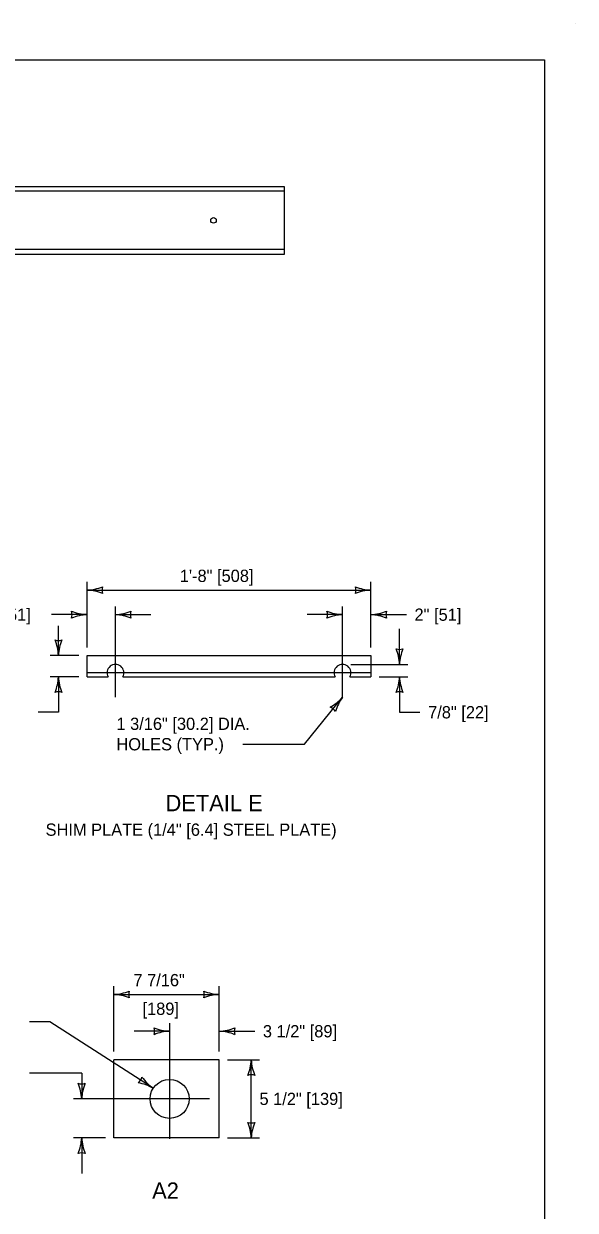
# Model space of a CAD drawing. Extents: x 49991.4 to 50021, y 49987.6 to 50011.4.
# Drawn here: x 50014.2 to 50016.9, y 49993.37 to 49999.18 of the extents above; entities that cross this region are included whole.
import ezdxf

# ---------------------------------------------------------------- set-up
doc = ezdxf.new("R2010")
doc.units = 0
for name, color, linetype in [('Level 1', 7, 'Continuous'), ('Level 2', 7, 'Continuous'), ('Level 3', 7, 'Continuous'), ('Level 4', 7, 'Continuous'), ('Level 5', 7, 'Continuous')]:
    doc.layers.add(name, color=color, linetype=linetype)

msp = doc.modelspace()

# ---------------------------------------------------------------- linework, layer by layer
at = {"layer": 'Level 1'}
for p, q in [((50016.9001, 49999.1756), (50016.9001, 49999.1756)), ((50015.4779, 49998.377), (50009.801, 49998.377)), ((50015.4779, 49998.0488), (50015.4779, 49998.377)), ((50009.7464, 49998.0488), (50015.4779, 49998.0488)), ((50014.5111, 49996.0841), (50015.9001, 49996.0841)), ((50014.5111, 49995.98), (50014.5111, 49996.0841)), ((50015.9001, 49996.0841), (50015.9001, 49995.98)), ((50014.5111, 49995.98), (50014.6137, 49995.98)), ((50014.6863, 49995.98), (50015.7249, 49995.98)), ((50015.7975, 49995.98), (50015.9001, 49995.98)), ((50015.158, 49994.1057), (50014.6415, 49994.1057)), ((50014.6415, 49993.7237), (50014.6415, 49994.1057)), ((50015.158, 49993.7237), (50015.158, 49994.1057)), ((50015.158, 49993.7237), (50014.6415, 49993.7237))]:
    msp.add_line(p, q, dxfattribs=at)
msp.add_lwpolyline([(49999.3835, 49998.9992), (50016.7501, 49998.9992), (50016.7501, 49987.7988), (49999.3835, 49987.7988)], close=True, dxfattribs=at)
for centre, radius in [((50015.1299, 49998.2132), 0.0136), ((50014.9149, 49993.9147), 0.0955)]:
    msp.add_circle(centre, radius, dxfattribs=at)
for centre in [(50014.65, 49995.9995), (50015.7612, 49995.9995)]:
    msp.add_arc(centre, 0.0412, 331.72619, 208.27381, dxfattribs=at)
at = {"layer": 'Level 3'}
for p, q in [((50014.5111, 49996.1241), (50014.5111, 49996.4441)), ((50015.9001, 49996.1241), (50015.9001, 49996.4441)), ((50014.5111, 49996.4041), (50015.9001, 49996.4041)), ((50014.5111, 49996.2841), (50014.3377, 49996.2841)), ((50014.65, 49996.2841), (50014.8235, 49996.2841)), ((50015.7612, 49996.2841), (50015.5877, 49996.2841)), ((50015.9001, 49996.2841), (50016.0735, 49996.2841)), ((50014.3711, 49996.0841), (50014.3711, 49996.2293)), ((50016.0401, 49996.0407), (50016.0401, 49996.2142)), ((50014.4711, 49996.0841), (50014.3311, 49996.0841)), ((50015.8012, 49996.0407), (50016.0801, 49996.0407)), ((50014.4711, 49995.98), (50014.3311, 49995.98)), ((50014.3711, 49995.98), (50014.3711, 49995.8065)), ((50015.9401, 49995.98), (50016.0801, 49995.98)), ((50016.0401, 49995.98), (50016.0401, 49995.8065)), ((50014.3711, 49995.8065), (50014.2711, 49995.8065)), ((50016.0401, 49995.8065), (50016.1401, 49995.8065)), ((50014.6415, 49994.1457), (50014.6415, 49994.4657)), ((50015.158, 49994.1457), (50015.158, 49994.4657)), ((50014.6415, 49994.4257), (50015.158, 49994.4257)), ((50014.3297, 49994.2911), (50014.2297, 49994.2911)), ((50014.8346, 49993.9664), (50014.3297, 49994.2911)), ((50014.9149, 49994.2457), (50014.7415, 49994.2457)), ((50015.158, 49994.2457), (50015.3314, 49994.2457)), ((50015.198, 49994.1057), (50015.3548, 49994.1057)), ((50015.3148, 49993.7237), (50015.3148, 49994.1057)), ((50014.4847, 49994.0399), (50014.2297, 49994.0399)), ((50014.4847, 49994.0399), (50014.4847, 49993.9147)), ((50014.6015, 49993.7237), (50014.4447, 49993.7237)), ((50014.4847, 49993.7237), (50014.4847, 49993.5503)), ((50015.198, 49993.7237), (50015.3548, 49993.7237))]:
    msp.add_line(p, q, dxfattribs=at)
msp.add_lwpolyline([(50015.2737, 49995.65), (50015.5749, 49995.65), (50015.7612, 49995.88)], dxfattribs=at)
for centre, radius, start, end in [((50014.4996, 49996.6368), 0.233, 272.82731, 292.07716), ((50014.6394, 49996.4041), 0.0548, 162.13882, 197.86118), ((50015.9092, 49996.6263), 0.2223, 247.45601, 267.63952), ((50015.7718, 49996.4041), 0.0548, 342.13882, 17.86118), ((50014.502, 49996.182), 0.2223, 67.45601, 87.63952), ((50015.9116, 49996.1714), 0.233, 92.82731, 112.07716), ((50014.5203, 49996.5063), 0.2223, 247.45601, 267.63952), ((50014.3829, 49996.2841), 0.0548, 342.13882, 17.86118), ((50014.6409, 49996.5063), 0.2223, 272.36048, 292.54399), ((50014.7782, 49996.2841), 0.0548, 162.13882, 197.86118), ((50015.7703, 49996.5063), 0.2223, 247.45601, 267.63952), ((50015.633, 49996.2841), 0.0548, 342.13882, 17.86118), ((50015.8909, 49996.5063), 0.2223, 272.36048, 292.54399), ((50016.0283, 49996.2841), 0.0548, 162.13882, 197.86118), ((50014.5226, 49996.0514), 0.233, 92.82731, 112.07716), ((50014.6385, 49996.0514), 0.233, 67.92284, 87.17269), ((50015.7727, 49996.0514), 0.233, 92.82731, 112.07716), ((50015.8886, 49996.0514), 0.233, 67.92284, 87.17269), ((50014.3711, 49996.2123), 0.0548, 252.13882, 287.86118), ((50014.1384, 49996.0726), 0.233, 2.82731, 22.07716), ((50014.5933, 49996.075), 0.2223, 157.45601, 177.63952), ((50015.8179, 49996.0316), 0.2223, 2.36048, 22.54399), ((50016.0401, 49996.1689), 0.0548, 252.13882, 287.86118), ((50016.2728, 49996.0292), 0.233, 157.92284, 177.17269), ((50014.1384, 49995.9915), 0.233, 337.92284, 357.17269), ((50014.5933, 49995.9891), 0.2223, 182.36048, 202.54399), ((50015.8179, 49995.9891), 0.2223, 337.45601, 357.63952), ((50016.2728, 49995.9915), 0.233, 182.82731, 202.07716), ((50014.3711, 49995.8517), 0.0548, 72.13882, 107.86118), ((50016.0401, 49995.8517), 0.0548, 72.13882, 107.86118), ((50015.5943, 49996.0269), 0.2223, 298.45409, 318.63759), ((50015.6805, 49995.7803), 0.0548, 33.13689, 68.85925), ((50015.9492, 49995.7424), 0.233, 143.82539, 163.07524), ((50014.63, 49994.6584), 0.233, 272.82731, 292.07716), ((50014.7697, 49994.4257), 0.0548, 162.13882, 197.86118), ((50015.1672, 49994.6478), 0.2223, 247.45601, 267.63952), ((50015.0298, 49994.4257), 0.0548, 342.13882, 17.86118), ((50014.6323, 49994.2035), 0.2223, 67.45601, 87.63952), ((50015.1695, 49994.1929), 0.233, 92.82731, 112.07716), ((50014.9241, 49994.4678), 0.2223, 247.45601, 267.63952), ((50014.7867, 49994.2457), 0.0548, 342.13882, 17.86118), ((50015.1488, 49994.4678), 0.2223, 272.36048, 292.54399), ((50015.2862, 49994.2457), 0.0548, 162.13882, 197.86118), ((50014.9264, 49994.0129), 0.233, 92.82731, 112.07716), ((50015.1465, 49994.0129), 0.233, 67.92284, 87.17269), ((50015.0821, 49994.1172), 0.233, 337.92284, 357.17269), ((50015.5369, 49994.1148), 0.2223, 182.36048, 202.54399), ((50015.3148, 49993.9774), 0.0548, 72.13882, 107.86118), ((50014.4847, 49994.0429), 0.0548, 252.13882, 287.86118), ((50014.252, 49993.9032), 0.233, 2.82731, 22.07716), ((50014.7068, 49993.9055), 0.2223, 157.45601, 177.63952), ((50014.7268, 49994.0357), 0.0548, 309.39, 345.11236), ((50014.7184, 49993.7644), 0.233, 60.07849, 79.32834), ((50014.9625, 49994.1482), 0.2223, 214.70719, 234.8907), ((50015.0927, 49993.7146), 0.2223, 2.36048, 22.54399), ((50015.3148, 49993.852), 0.0548, 252.13882, 287.86118), ((50015.5475, 49993.7123), 0.233, 157.92284, 177.17269), ((50014.2626, 49993.7329), 0.2223, 337.45601, 357.63952), ((50014.7174, 49993.7352), 0.233, 182.82731, 202.07716), ((50014.4847, 49993.5955), 0.0548, 72.13882, 107.86118)]:
    msp.add_arc(centre, radius, start, end, dxfattribs=at)
at = {"layer": 'Level 4'}
for p, q in [((50015.4779, 49998.3555), (50009.801, 49998.3555)), ((50015.4779, 49998.071), (50009.801, 49998.071))]:
    msp.add_line(p, q, dxfattribs=at)
at = {"layer": 'Level 5'}
for p, q in [((50014.65, 49995.88), (50014.65, 49996.3241)), ((50015.7612, 49995.88), (50015.7612, 49996.3241)), ((50015.9024, 49995.9995), (50014.5088, 49995.9995)), ((50014.9149, 49994.2856), (50014.9149, 49993.7192)), ((50015.1104, 49993.9147), (50014.4447, 49993.9147))]:
    msp.add_line(p, q, dxfattribs=at)

# ---------------------------------------------------------------- texts
at = {"layer": 'Level 2'}
for s, height, p in [('1\'-8" [508]', 0.06, (50014.965, 49996.4441)), ('2"[51]', 0.06, (50014.0287, 49996.2541)), ('2" [51]', 0.06, (50016.1135, 49996.2541)), ('7/8" [22]', 0.06, (50016.1801, 49995.7765)), ('1 3/16" [30.2] DIA.', 0.06, (50014.6548, 49995.72)), ('HOLES (TYP.)', 0.06, (50014.6548, 49995.62)), ('DETAIL E', 0.08, (50014.8949, 49995.3221)), ('SHIM PLATE (1/4" [6.4] STEEL PLATE)', 0.06, (50014.3082, 49995.2021)), ('7 7/16"', 0.06, (50014.7381, 49994.4657)), ('[189]', 0.06, (50014.7824, 49994.3257)), ('3 1/2" [89]', 0.06, (50015.3714, 49994.2157)), ('5 1/2" [139]', 0.06, (50015.3548, 49993.8847)), ('A2', 0.08, (50014.8296, 49993.4258))]:
    msp.add_text(s, height=height, dxfattribs=at).set_placement(p)

doc.saveas('drawing.dxf')
